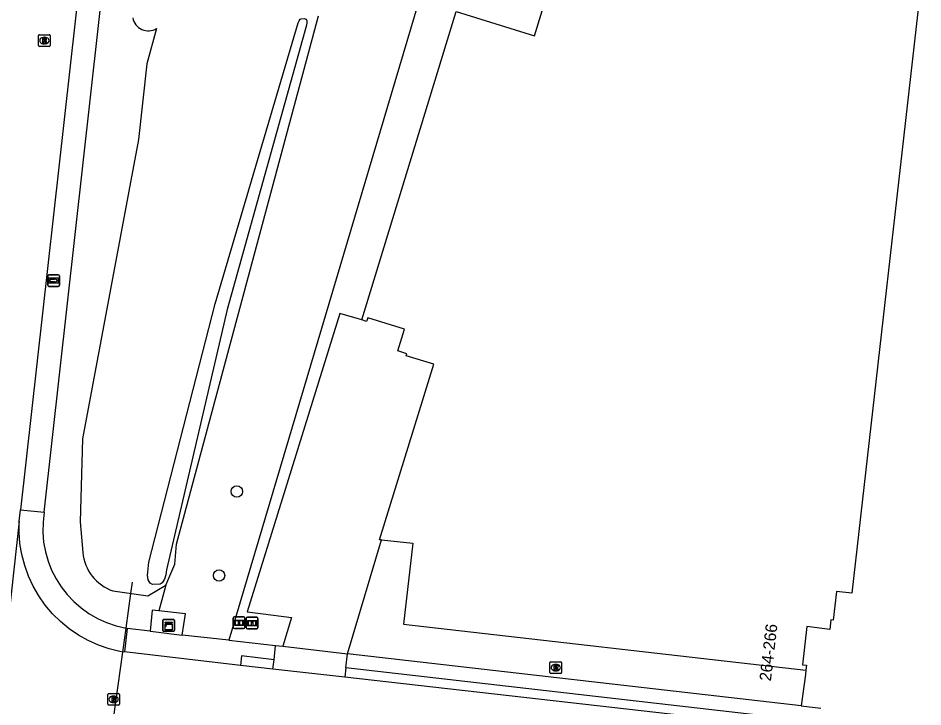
# Model space of a CAD drawing. Extents: x 161389 to 162585, y 388479 to 389761.
# Drawn here: x 162354.5 to 162432, y 388797.2 to 388856.1 of the extents above; entities that cross this region are included whole.
import ezdxf

# ---------------------------------------------------------------- set-up
doc = ezdxf.new("R2010")
doc.units = 0
for name, color, linetype in [('IMGEO_Boom', 7, 'Continuous'), ('IMGEO_Duiker', 7, 'Continuous'), ('IMGEO_Groenvoorziening', 7, 'Continuous'), ('IMGEO_Informatiebord', 7, 'Continuous'), ('IMGEO_Kast', 7, 'Continuous'), ('IMGEO_Pand', 7, 'Continuous'), ('IMGEO_Pand_nummerreeks', 7, 'Continuous'), ('IMGEO_Parkeervlak_open', 7, 'Continuous'), ('IMGEO_Rijbaan_lokaal_gesloten', 7, 'Continuous'), ('IMGEO_Rioolput', 7, 'Continuous'), ('IMGEO_Voetpad_open', 7, 'Continuous'), ('IMGEO_Waterloop', 7, 'Continuous'), ('IMGEO_Wegwijzer', 7, 'Continuous')]:
    doc.layers.add(name, color=color, linetype=linetype)

msp = doc.modelspace()

# ---------------------------------------------------------------- linework, layer by layer
at = {"layer": 'IMGEO_Boom'}
for centre in [(162373.229, 388815.659), (162371.707, 388808.472)]:
    msp.add_circle(centre, 0.489, dxfattribs=at)
at = {"layer": 'IMGEO_Duiker'}
msp.add_lwpolyline([(162361.55, 388788.054), (162361.716, 388789.259), (162362.478, 388794.795), (162363.461, 388801.928), (162363.744, 388803.982), (162364.151, 388806.939), (162364.285, 388807.91)], dxfattribs=at)
at = {"layer": 'IMGEO_Groenvoorziening'}
for points in [[(162391.857, 388867.872), (162372.558, 388802.943)], [(162367.141, 388807.636), (162367.935, 388809.448), (162368.059, 388811.153), (162380.214, 388856.331)], [(162366.359, 388855.245), (162365.519, 388852.226), (162364.801, 388845.747), (162360.025, 388820.155), (162359.821, 388813.059), (162360.04, 388810.447)], [(162362.622, 388807.156), (162365.602, 388806.733), (162367.141, 388807.636)], [(162367.141, 388807.636), (162366.551, 388805.446)], [(162421.939, 388800.373), (162421.892, 388800.017), (162421.541, 388797.334)]]:
    msp.add_lwpolyline(points, dxfattribs=at)
for centre, radius, start, end in [((162365.665, 388856.428), 1.372, 191.02807, 300.39744), ((162363.898, 388810.815), 3.875, 185.45312, 250.77978)]:
    msp.add_arc(centre, radius, start, end, dxfattribs=at)
at = {"layer": 'IMGEO_Informatiebord'}
for p, q in [((162372.921, 388804.031), (162372.921, 388804.831)), ((162372.921, 388804.831), (162372.921, 388804.031)), ((162373.021, 388804.931), (162373.811, 388804.931)), ((162373.811, 388804.931), (162373.021, 388804.931)), ((162373.911, 388804.831), (162373.911, 388804.031)), ((162373.911, 388804.031), (162373.911, 388804.831)), ((162374.041, 388804.004), (162374.041, 388804.804)), ((162374.041, 388804.804), (162374.041, 388804.004)), ((162374.141, 388804.904), (162374.931, 388804.904)), ((162374.931, 388804.904), (162374.141, 388804.904)), ((162375.031, 388804.804), (162375.031, 388804.004)), ((162375.031, 388804.004), (162375.031, 388804.804)), ((162373.811, 388803.931), (162373.021, 388803.931)), ((162373.021, 388803.931), (162373.811, 388803.931)), ((162374.931, 388803.904), (162374.141, 388803.904)), ((162374.141, 388803.904), (162374.931, 388803.904))]:
    msp.add_line(p, q, dxfattribs=at)
for points in [[(162373.022, 388804.663), (162373.81, 388804.663), (162373.81, 388804.199), (162373.022, 388804.199), (162373.022, 388804.663)], [(162373.087, 388804.598), (162373.087, 388804.264), (162373.362, 388804.264), (162373.363, 388804.477), (162373.467, 388804.478), (162373.468, 388804.264), (162373.745, 388804.264), (162373.745, 388804.598), (162373.469, 388804.598), (162373.469, 388804.518), (162373.363, 388804.518), (162373.363, 388804.598), (162373.087, 388804.598)], [(162374.142, 388804.636), (162374.93, 388804.636), (162374.93, 388804.172), (162374.142, 388804.172), (162374.142, 388804.636)], [(162374.207, 388804.571), (162374.207, 388804.237), (162374.482, 388804.237), (162374.483, 388804.45), (162374.587, 388804.451), (162374.588, 388804.237), (162374.865, 388804.237), (162374.865, 388804.571), (162374.589, 388804.571), (162374.589, 388804.491), (162374.483, 388804.491), (162374.483, 388804.571), (162374.207, 388804.571)]]:
    msp.add_lwpolyline(points, dxfattribs=at)
for centre, start, end in [((162373.021, 388804.831), 90, 180), ((162373.021, 388804.831), 90, 180), ((162373.811, 388804.831), 0, 90), ((162373.811, 388804.831), 360, 90), ((162374.141, 388804.804), 90, 180), ((162374.141, 388804.804), 90, 180), ((162374.931, 388804.804), 0, 90), ((162374.931, 388804.804), 360, 90), ((162373.021, 388804.031), 180, 270), ((162373.021, 388804.031), 180, 270), ((162373.811, 388804.031), 270, 0), ((162373.811, 388804.031), 270, 0), ((162374.141, 388804.004), 180, 270), ((162374.141, 388804.004), 180, 270), ((162374.931, 388804.004), 270, 0), ((162374.931, 388804.004), 270, 0)]:
    msp.add_arc(centre, 0.1, start, end, dxfattribs=at)
at = {"layer": 'IMGEO_Kast'}
for p, q in [((162366.888, 388803.777), (162366.888, 388804.618)), ((162366.888, 388804.618), (162366.888, 388803.777)), ((162366.963, 388804.702), (162367.804, 388804.702)), ((162367.804, 388804.702), (162366.963, 388804.702)), ((162367.888, 388804.627), (162367.888, 388803.786)), ((162367.888, 388803.786), (162367.888, 388804.627)), ((162367.813, 388803.702), (162366.972, 388803.702)), ((162366.972, 388803.702), (162367.813, 388803.702))]:
    msp.add_line(p, q, dxfattribs=at)
for points in [[(162367.083, 388804.492), (162367.683, 388804.492), (162367.683, 388804.407), (162367.083, 388804.407), (162367.083, 388804.492)], [(162367.083, 388804.317), (162367.683, 388804.317), (162367.683, 388803.828), (162367.083, 388803.828), (162367.083, 388804.317)]]:
    msp.add_lwpolyline(points, dxfattribs=at)
msp.add_circle((162367.167, 388804.166), 0.0377, dxfattribs=at)
for centre, start, end in [((162366.966, 388804.624), 92.4484, 184.28452), ((162366.966, 388804.624), 92.4484, 184.28452), ((162367.81, 388804.624), 2.4484, 94.28452), ((162367.81, 388804.624), 2.4484, 94.28452), ((162366.966, 388803.78), 182.4484, 274.28452), ((162366.966, 388803.78), 182.4484, 274.28452), ((162367.81, 388803.78), 272.4484, 4.28452), ((162367.81, 388803.78), 272.4484, 4.28452)]:
    msp.add_arc(centre, 0.0779, start, end, dxfattribs=at)
at = {"layer": 'IMGEO_Pand'}
for points in [[(162383.919, 388830.342), (162392.007, 388856.692), (162398.712, 388854.634), (162401.565, 388863.931), (162427.905, 388860.918)], [(162427.905, 388860.918), (162431.951, 388860.46), (162425.867, 388806.95), (162424.566, 388807.108), (162424.267, 388804.656), (162424.078, 388804.678), (162423.978, 388803.864), (162422.022, 388804.102), (162421.644, 388800.836), (162421.982, 388800.802), (162421.939, 388800.373)], [(162385.61, 388811.516), (162385.443, 388811.533), (162390.077, 388826.541), (162387.727, 388827.265), (162387.77, 388827.442), (162386.998, 388827.681), (162387.579, 388829.553), (162384.428, 388830.506), (162384.333, 388830.182), (162383.919, 388830.342)], [(162385.61, 388811.516), (162388.282, 388811.244), (162387.48, 388804.31), (162421.939, 388800.373)]]:
    msp.add_lwpolyline(points, dxfattribs=at)
at = {"layer": 'IMGEO_Parkeervlak_open'}
for points in [[(162383.919, 388830.342), (162383.532, 388830.458), (162382.047, 388830.873), (162374.122, 388805.367), (162375.474, 388805.196), (162377.914, 388804.888), (162377.177, 388802.419)], [(162382.688, 388801.778), (162385.61, 388811.516)]]:
    msp.add_lwpolyline(points, dxfattribs=at)
at = {"layer": 'IMGEO_Rijbaan_lokaal_gesloten'}
for points in [[(162361.659, 388872.226), (162361.541, 388871.709), (162360.606, 388866.537), (162360.509, 388865.779), (162360.209, 388863.109), (162359.887, 388860.235), (162354.707, 388814.075)], [(162354.609, 388813.12), (162354.707, 388814.075)], [(162354.609, 388813.12), (162351.586, 388785.803)], [(162363.603, 388801.935), (162363.461, 388801.928), (162363.22, 388801.973), (162362.288, 388802.204), (162361.381, 388802.516), (162360.504, 388802.908), (162359.667, 388803.377), (162358.875, 388803.919), (162358.134, 388804.53), (162357.451, 388805.204), (162356.831, 388805.937), (162356.278, 388806.722), (162355.798, 388807.553), (162355.395, 388808.424), (162355.07, 388809.328), (162354.828, 388810.256), (162354.669, 388811.203), (162354.596, 388812.16), (162354.609, 388813.12)], [(162373.536, 388800.784), (162363.603, 388801.935)], [(162376.319, 388800.468), (162373.536, 388800.784)], [(162382.484, 388799.768), (162376.319, 388800.468)], [(162423.146, 388795.15), (162382.484, 388799.768)]]:
    msp.add_lwpolyline(points, dxfattribs=at)
at = {"layer": 'IMGEO_Rioolput'}
for p, q in [((162356.253, 388853.791), (162356.253, 388854.643)), ((162356.328, 388854.717), (162357.18, 388854.717)), ((162357.254, 388854.643), (162357.254, 388853.791)), ((162356.764, 388853.937), (162356.739, 388853.937)), ((162356.741, 388854.497), (162356.766, 388854.497)), ((162357.18, 388853.717), (162356.328, 388853.717)), ((162400.025, 388800.169), (162400.025, 388801.021)), ((162400.1, 388801.095), (162400.952, 388801.095)), ((162400.513, 388800.875), (162400.538, 388800.875)), ((162401.026, 388801.021), (162401.026, 388800.169)), ((162400.952, 388800.095), (162400.1, 388800.095)), ((162400.536, 388800.315), (162400.511, 388800.315)), ((162362.181, 388797.458), (162362.181, 388798.31)), ((162362.256, 388798.384), (162363.108, 388798.384)), ((162362.669, 388798.164), (162362.694, 388798.164)), ((162363.182, 388798.31), (162363.182, 388797.458)), ((162363.108, 388797.384), (162362.256, 388797.384)), ((162362.692, 388797.604), (162362.667, 388797.604))]:
    msp.add_line(p, q, dxfattribs=at)
for points in [[(162356.253, 388853.791), (162356.253, 388854.643)], [(162356.328, 388854.717), (162357.18, 388854.717)], [(162357.254, 388854.643), (162357.254, 388853.791)], [(162356.842, 388854.415), (162356.59, 388854.417), (162356.59, 388854.017)], [(162356.59, 388854.017), (162356.714, 388854.017), (162356.714, 388854.179), (162356.725, 388854.179)], [(162356.768, 388854.336), (162356.714, 388854.336), (162356.714, 388854.255)], [(162356.714, 388854.255), (162356.766, 388854.255)], [(162356.772, 388854.15), (162356.843, 388854.017), (162356.983, 388854.017), (162356.918, 388854.143)], [(162357.18, 388853.717), (162356.328, 388853.717)], [(162400.025, 388800.169), (162400.025, 388801.021)], [(162400.1, 388801.095), (162400.952, 388801.095)], [(162400.614, 388800.793), (162400.362, 388800.795), (162400.362, 388800.395)], [(162400.362, 388800.395), (162400.486, 388800.395), (162400.486, 388800.557), (162400.497, 388800.557)], [(162400.54, 388800.714), (162400.486, 388800.714), (162400.486, 388800.633)], [(162400.486, 388800.633), (162400.538, 388800.633)], [(162400.544, 388800.528), (162400.615, 388800.395), (162400.755, 388800.395), (162400.69, 388800.521)], [(162401.026, 388801.021), (162401.026, 388800.169)], [(162400.952, 388800.095), (162400.1, 388800.095)], [(162362.181, 388797.458), (162362.181, 388798.31)], [(162362.256, 388798.384), (162363.108, 388798.384)], [(162363.182, 388798.31), (162363.182, 388797.458)], [(162363.108, 388797.384), (162362.256, 388797.384)], [(162362.77, 388798.082), (162362.518, 388798.084), (162362.518, 388797.684)], [(162362.518, 388797.684), (162362.642, 388797.684), (162362.642, 388797.846), (162362.653, 388797.846)], [(162362.696, 388798.003), (162362.642, 388798.003), (162362.642, 388797.922)], [(162362.642, 388797.922), (162362.694, 388797.922)], [(162362.7, 388797.817), (162362.771, 388797.684), (162362.911, 388797.684), (162362.846, 388797.81)]]:
    msp.add_lwpolyline(points, dxfattribs=at)
for centre, radius, start, end in [((162356.33, 388854.641), 0.0765, 91.55205, 178.44795), ((162356.33, 388854.641), 0.0765, 91.55205, 178.44795), ((162357.178, 388854.641), 0.0765, 1.55205, 88.44795), ((162357.178, 388854.641), 0.0765, 1.55205, 88.44795), ((162356.724, 388854.126), 0.0533, 26.02933, 88.69889), ((162356.75, 388854.444), 0.19, 274.7715, 282.96867), ((162356.774, 388854.24), 0.0964, 77.00612, 93.18647), ((162356.788, 388854.297), 0.0378, 276.66336, 79.67722), ((162356.841, 388854.305), 0.109, 350.36119, 89.41601), ((162356.839, 388854.305), 0.112, 277.58423, 350.98172), ((162356.823, 388854.09), 0.108, 29.51342, 73.79051), ((162356.33, 388853.793), 0.0765, 181.55205, 268.44795), ((162356.33, 388853.793), 0.0765, 181.55205, 268.44795), ((162357.178, 388853.793), 0.0765, 271.55205, 358.44795), ((162357.178, 388853.793), 0.0765, 271.55205, 358.44795), ((162400.102, 388801.019), 0.0765, 91.55205, 178.44795), ((162400.102, 388801.019), 0.0765, 91.55205, 178.44795), ((162400.496, 388800.504), 0.0533, 26.02933, 88.69889), ((162400.522, 388800.822), 0.19, 274.7715, 282.96867), ((162400.546, 388800.618), 0.0964, 77.00612, 93.18647), ((162400.56, 388800.675), 0.0378, 276.66336, 79.67722), ((162400.613, 388800.683), 0.109, 350.36119, 89.41601), ((162400.611, 388800.683), 0.112, 277.58423, 350.98172), ((162400.595, 388800.468), 0.108, 29.51342, 73.79051), ((162400.95, 388801.019), 0.0765, 1.55205, 88.44795), ((162400.95, 388801.019), 0.0765, 1.55205, 88.44795), ((162400.102, 388800.171), 0.0765, 181.55205, 268.44795), ((162400.102, 388800.171), 0.0765, 181.55205, 268.44795), ((162400.95, 388800.171), 0.0765, 271.55205, 358.44795), ((162400.95, 388800.171), 0.0765, 271.55205, 358.44795), ((162362.258, 388798.308), 0.0765, 91.55205, 178.44795), ((162362.258, 388798.308), 0.0765, 91.55205, 178.44795), ((162363.106, 388798.308), 0.0765, 1.55205, 88.44795), ((162363.106, 388798.308), 0.0765, 1.55205, 88.44795), ((162362.258, 388797.46), 0.0765, 181.55205, 268.44795), ((162362.258, 388797.46), 0.0765, 181.55205, 268.44795), ((162362.652, 388797.793), 0.0533, 26.02933, 88.69889), ((162362.678, 388798.111), 0.19, 274.7715, 282.96867), ((162362.702, 388797.907), 0.0964, 77.00612, 93.18647), ((162362.716, 388797.964), 0.0378, 276.66336, 79.67722), ((162362.769, 388797.972), 0.109, 350.36119, 89.41601), ((162362.767, 388797.972), 0.112, 277.58423, 350.98172), ((162362.751, 388797.757), 0.108, 29.51342, 73.79051), ((162363.106, 388797.46), 0.0765, 271.55205, 358.44795), ((162363.106, 388797.46), 0.0765, 271.55205, 358.44795)]:
    msp.add_arc(centre, radius, start, end, dxfattribs=at)
for centre, major_axis, ratio, start_param, end_param in [((162356.74, 388854.217), (-0.387, 0.002), 0.722429, 4.712389, 7.853982), ((162356.765, 388854.217), (-0.39, 0.002), 0.717154, 1.570796, 4.712389), ((162400.512, 388800.595), (-0.387, 0.002), 0.722429, 4.712389, 7.853982), ((162400.537, 388800.595), (-0.39, 0.002), 0.717154, 1.570796, 4.712389), ((162362.668, 388797.884), (-0.387, 0.002), 0.722429, 4.712389, 7.853982), ((162362.693, 388797.884), (-0.39, 0.002), 0.717154, 1.570796, 4.712389)]:
    msp.add_ellipse(centre, major_axis=major_axis, ratio=ratio, start_param=start_param, end_param=end_param, dxfattribs=at)
at = {"layer": 'IMGEO_Voetpad_open'}
for points in [[(162356.744, 388813.903), (162362.048, 388861.405), (162362.437, 388864.885), (162362.617, 388866.281), (162363.642, 388871.781), (162364.588, 388875.934)], [(162354.707, 388814.075), (162356.744, 388813.903)], [(162366.551, 388805.446), (162365.996, 388805.509), (162365.806, 388803.721)], [(162368.553, 388803.357), (162368.834, 388805.186), (162366.551, 388805.446)], [(162363.842, 388803.946), (162363.603, 388801.935)], [(162363.842, 388803.946), (162363.744, 388803.982)], [(162365.806, 388803.721), (162363.842, 388803.946)], [(162365.806, 388803.721), (162366.079, 388803.689), (162368.553, 388803.357)], [(162372.558, 388802.943), (162368.553, 388803.357)], [(162372.558, 388802.943), (162376.55, 388802.484)], [(162376.411, 388801.273), (162376.55, 388802.484)], [(162376.55, 388802.484), (162377.177, 388802.419)], [(162377.177, 388802.419), (162382.688, 388801.778)], [(162376.411, 388801.273), (162373.639, 388801.6), (162373.536, 388800.784)], [(162376.319, 388800.468), (162376.411, 388801.273)], [(162382.567, 388800.591), (162382.688, 388801.778)], [(162421.541, 388797.334), (162382.688, 388801.778)], [(162382.567, 388800.591), (162382.484, 388799.768)], [(162423.063, 388795.942), (162382.567, 388800.591)], [(162421.541, 388797.334), (162423.214, 388797.141)]]:
    msp.add_lwpolyline(points, dxfattribs=at)
msp.add_arc((162365.22, 388812.454), 8.599, 170.29795, 260.11365, dxfattribs=at)
at = {"layer": 'IMGEO_Waterloop'}
msp.add_lwpolyline([(162378.48, 388855.748), (162378.559, 388855.909), (162378.663, 388856.041), (162378.739, 388856.089), (162378.997, 388856.112), (162379.155, 388856.038), (162379.223, 388855.912), (162379.231, 388855.739), (162379.206, 388855.544), (162372.388, 388831.21), (162367.213, 388808.959), (162367.142, 388808.534), (162367.034, 388808.151), (162366.849, 388807.85), (162366.671, 388807.719), (162365.999, 388807.709), (162365.824, 388807.819), (162365.627, 388808.091), (162365.578, 388808.49), (162365.606, 388808.764), (162365.698, 388809.605), (162371.382, 388831.713), (162378.48, 388855.748)], dxfattribs=at)
at = {"layer": 'IMGEO_Wegwijzer'}
for p, q in [((162357.049, 388833.297), (162357.049, 388834.097)), ((162357.049, 388834.097), (162357.049, 388833.297)), ((162357.149, 388834.197), (162357.939, 388834.197)), ((162357.939, 388834.197), (162357.149, 388834.197)), ((162358.039, 388834.097), (162358.039, 388833.297)), ((162358.039, 388833.297), (162358.039, 388834.097)), ((162357.939, 388833.197), (162357.149, 388833.197)), ((162357.149, 388833.197), (162357.939, 388833.197))]:
    msp.add_line(p, q, dxfattribs=at)
for points in [[(162357.15, 388833.929), (162357.938, 388833.929), (162357.938, 388833.465), (162357.15, 388833.465), (162357.15, 388833.929)], [(162357.215, 388833.781), (162357.215, 388833.697), (162357.215, 388833.613), (162357.626, 388833.613), (162357.626, 388833.53), (162357.873, 388833.697), (162357.626, 388833.864), (162357.626, 388833.781), (162357.215, 388833.781)]]:
    msp.add_lwpolyline(points, dxfattribs=at)
for centre, start, end in [((162357.149, 388834.097), 90, 180), ((162357.149, 388834.097), 90, 180), ((162357.939, 388834.097), 0, 90), ((162357.939, 388834.097), 360, 90), ((162357.149, 388833.297), 180, 270), ((162357.149, 388833.297), 180, 270), ((162357.939, 388833.297), 270, 0), ((162357.939, 388833.297), 270, 0)]:
    msp.add_arc(centre, 0.1, start, end, dxfattribs=at)

# ---------------------------------------------------------------- texts
at = {"layer": 'IMGEO_Pand_nummerreeks'}
msp.add_text('264-266', height=1, rotation=83.39808, dxfattribs=at).set_placement((162418.941, 388799.402))

doc.saveas('drawing.dxf')
